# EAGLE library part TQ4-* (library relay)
LOW PROFILE 2 FORM C RELAY NAiS Source: http://www.mew-europe.com/.. en_ds_61020_0001.pdf
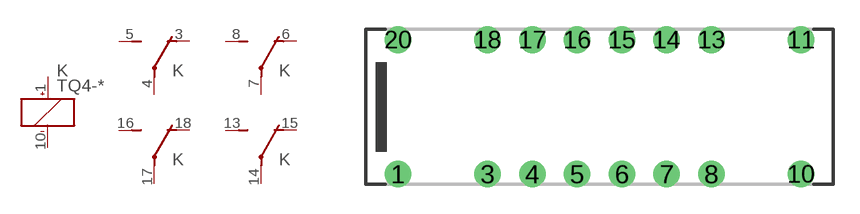
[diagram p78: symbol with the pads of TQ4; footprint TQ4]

Designator prefix K; gates _=K+- 1=U 2=U 3=U 4=U

## TQ4-3V (MPN: TQ4-3V; OC_FARNELL: unknown; OC_NEWARK: 13P9240), TQ4-4.5V (MPN: TQ4-4.5V; OC_FARNELL: unknown; OC_NEWARK: 13P9241), TQ4-5V (MF: AROMAT/ MATSUSHITA; MPN: TQ4-5V; OC_FARNELL: 1448362; OC_NEWARK: 67K1293), TQ4-6V (OC_FARNELL: unknown; OC_NEWARK: unknown), TQ4-9V (OC_FARNELL: unknown; OC_NEWARK: unknown), TQ4-12C (OC_FARNELL: unknown; OC_NEWARK: unknown), TQ4-24V (MF: AROMAT/ MATSUSHITA; MPN: TQ4-24V; OC_FARNELL: 1608334; OC_NEWARK: 64K3210), TQ4-48V (OC_FARNELL: unknown; OC_NEWARK: unknown)  [TQ4]
1  _:+  pas
3  1:O  pas
4  1:P  pas
5  1:S  pas
6  2:O  pas
7  2:P  pas
8  2:S  pas
10  _:-  pas
13  4:S  pas
14  4:P  pas
15  4:O  pas
16  3:S  pas
17  3:P  pas
18  3:O  pas

## TQ4-3VL- (OC_FARNELL: unknown; OC_NEWARK: unknown), TQ4-4.5VL- (OC_FARNELL: unknown; OC_NEWARK: unknown), TQ4-5VL- (OC_FARNELL: 1448362; OC_NEWARK: unknown), TQ4-6VL- (OC_FARNELL: unknown; OC_NEWARK: unknown), TQ4-9VL- (OC_FARNELL: unknown; OC_NEWARK: unknown), TQ4-12VL- (OC_FARNELL: unknown; OC_NEWARK: unknown), TQ4-24VL- (OC_FARNELL: unknown; OC_NEWARK: unknown)  [TQ4]
1  _:-  pas
3  1:O  pas
4  1:P  pas
5  1:S  pas
6  2:O  pas
7  2:P  pas
8  2:S  pas
10  _:+  pas
13  4:S  pas
14  4:P  pas
15  4:O  pas
16  3:S  pas
17  3:P  pas
18  3:O  pas

## Footprint TQ4 (pad centres in mm)
LOW PROFILE 2 FORM C RELAY NAiS Source: http://www.mew-europe.com/.. en_ds_61020_0001.pdf
drill 1 round: 1 -11.43,-3.81; 3 -6.35,-3.81; 4 -3.81,-3.81; 5 -1.27,-3.81; 6 1.27,-3.81; 7 3.81,-3.81; 8 6.35,-3.81; 10 11.43,-3.81; 11 11.43,3.81; 13 6.35,3.81; 14 3.81,3.81; 15 1.27,3.81; 16 -1.27,3.81; 17 -3.81,3.81; 18 -6.35,3.81; 20 -11.43,3.81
